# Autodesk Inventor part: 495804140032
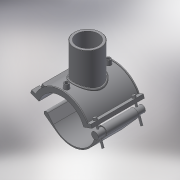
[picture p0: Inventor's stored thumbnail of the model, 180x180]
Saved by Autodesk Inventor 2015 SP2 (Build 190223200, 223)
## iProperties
Created: 2017-07
Part Number: 495804140032
Material: Generic
Description: PLASSON BRANCH SADDLE 140-32
Document SubType Name: Modeling
Designer: KIM
Density: 1 g/cm^3
Appearance: Default
Author: KIM
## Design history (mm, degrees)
derived "495804.ipt"
feature "Solid1::495804.ipt"
feature "Solid2::495804.ipt"
tag "TaggingFeature1"
body "Solid1"
body "Solid2"
other parameters: "d3" = 35, "d4" = 118, "d5" = 0, "d6" = 0.1, "d8" = 0, "d19" = 6, "d20" = 6, "d21" = 70.8, "d23" = 0, "d24" = 35.4, "d26" = 0, "d27" = 3, "d28" = 3, "d29" = 3, "d30" = 46.66667, "d31" = 6, "d32" = 0, "d33" = 0, "d34" = 0.6, "d40" = 83.2, "d41" = 35.2, "d43" = 0, "d45" = 0, "d47" = 139, "d48" = 32, "d50" = 0, "d70" = 15, "d72" = 0, "d73" = 6, "d75" = 5, "d76" = 0, "d77" = 7, "d79" = 15, "d80" = 47.2, "d82" = 5 deg, "d84" = 4, "d85" = 14, "d86" = 0, "d87" = 3, "d88" = 0, "d89" = 1, "d90" = 1, "d91" = 94.4, "d92" = 0, "d93" = 0.5, "d94" = 73.68421, "d96" = 163.2, "d97" = 2.36, "d98" = 0, "d102" = 0.96, "d103" = 25.6, "d105" = 0, "d109" = -19.66667, "d117" = 0.32, "d120" = 140 deg, "d121" = 24.228, "d122" = 20 deg, "d124" = 96, "d126" = 0, "d143" = 147, "d150" = 25.2, "d159" = 4, "d161" = 3.5, "d162" = 70.8, "d163" = 0, "d167" = 28, "d168" = 72.72727, "d173" = 1, "d176" = 20 deg, "d177" = 9.8, "d180" = 0, "d185" = 38.35, "d186" = 38.35, "d188" = 6, "d189" = 9.8, "d190" = 0, "d202" = 0, "d216" = 106.2, "d217" = 0, "d221" = 43.66, "d222" = 9.8, "d223" = 5.88, "d225" = 5.88, "d227" = 20.16, "d230" = 86.8, "d236" = 20 deg, "d237" = 87, "d238" = 20 deg, "d239" = 9.8, "H_" = 59, "L_" = 118, "d_t" = 6, "d_1" = 32, "H_1" = 49, "d148" = 3.5, "d160" = 3.5
